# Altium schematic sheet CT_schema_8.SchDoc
size 391 x 238 mm
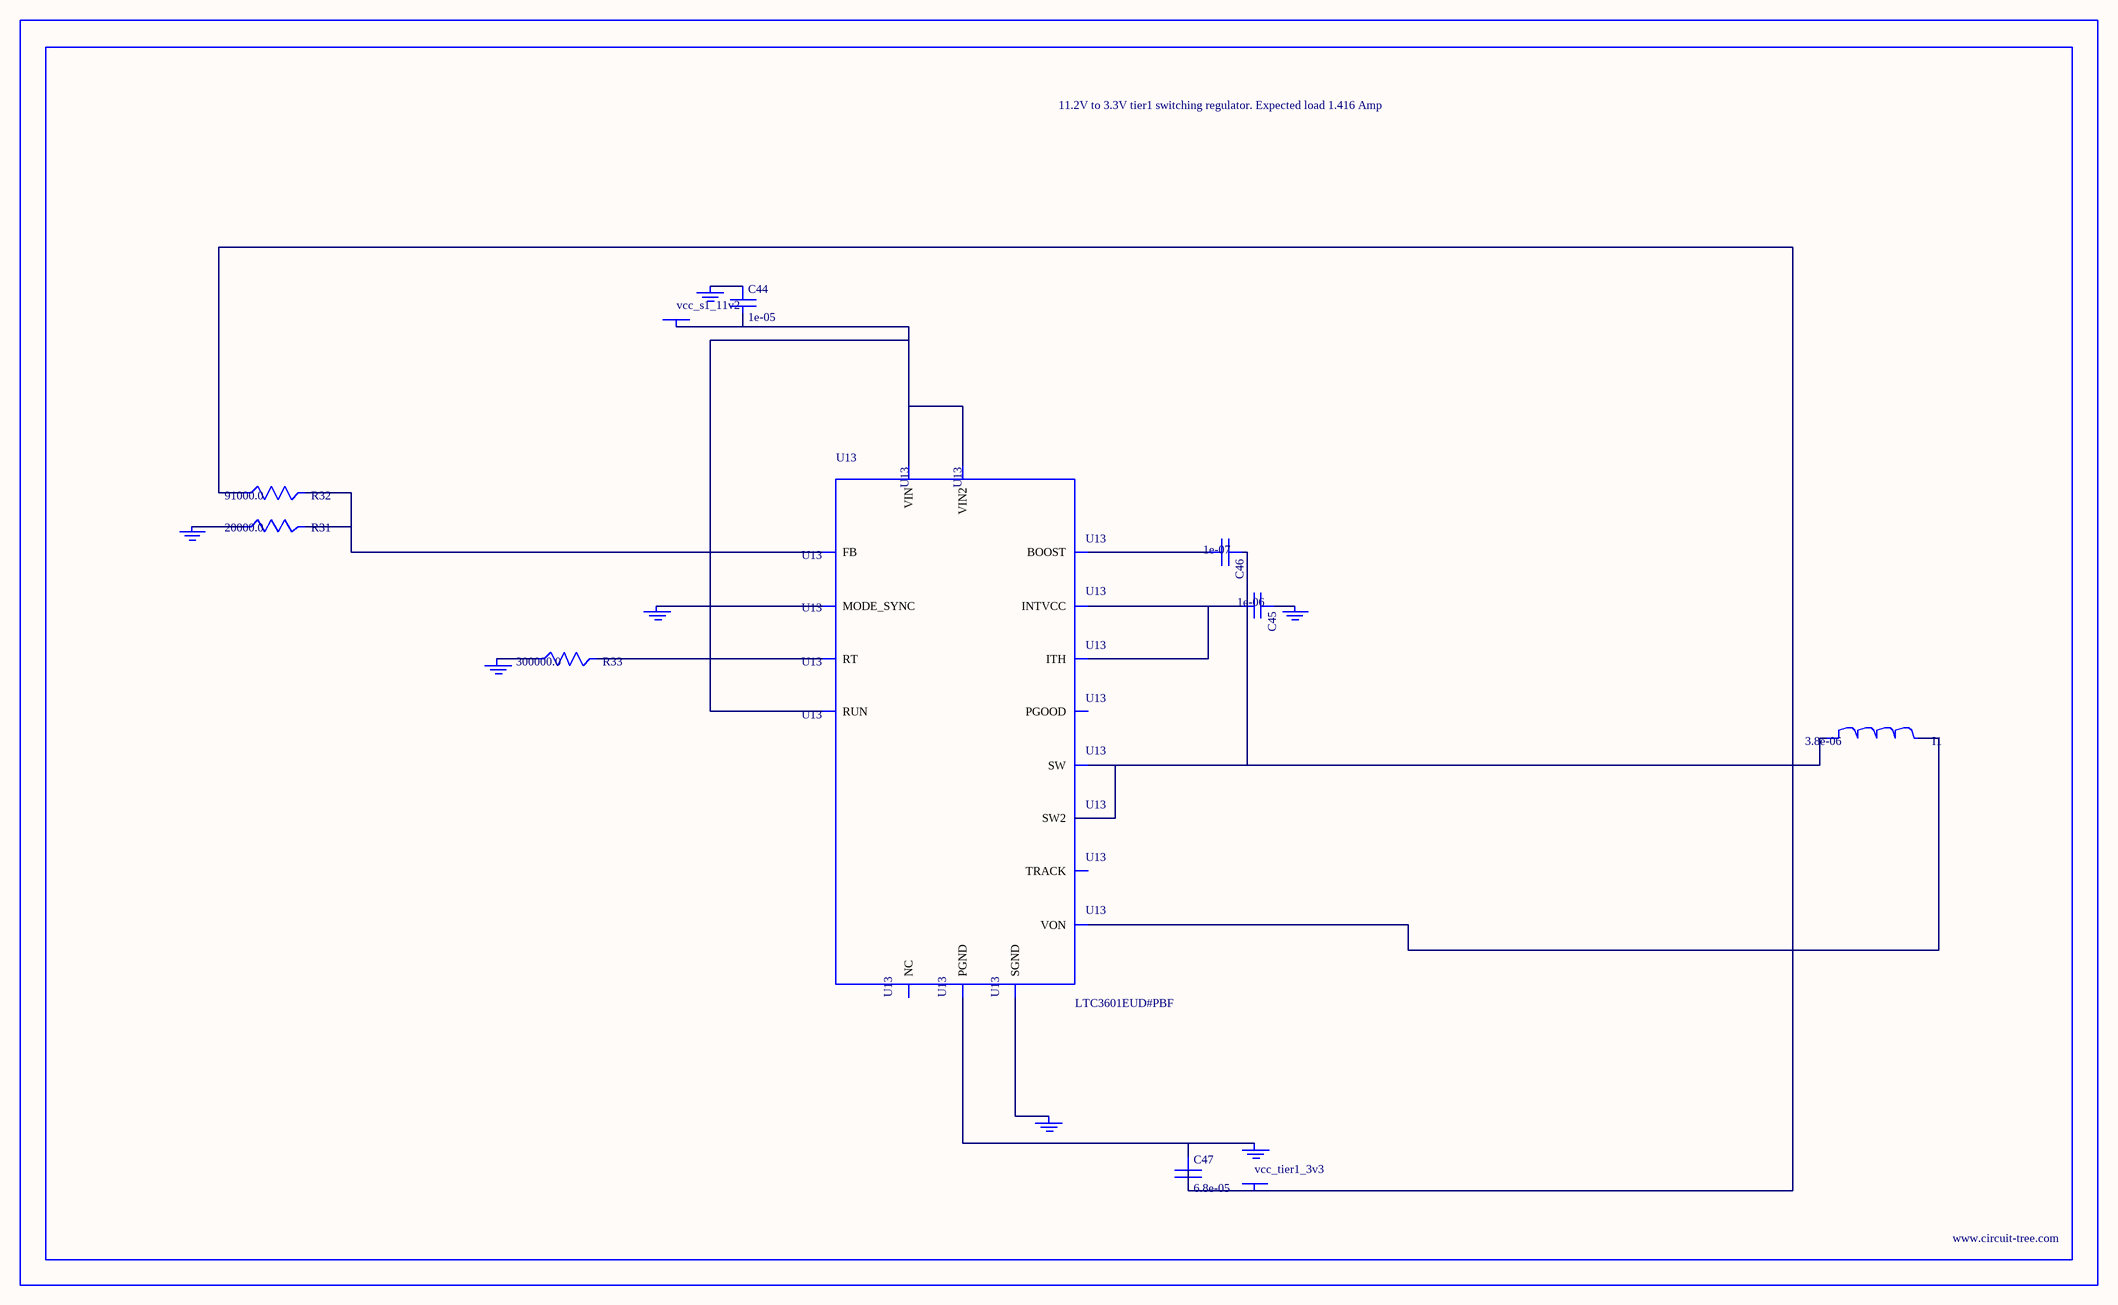
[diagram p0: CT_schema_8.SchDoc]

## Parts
BORDER7  (no value)
C44  1e-05  [C0805]
C45  1e-06  [C0603]
C46  1e-07  [C0402]
C47  6.8e-05  [2220]
GND_INSTANCE_7_0  (no value)
GND_INSTANCE_7_1  (no value)
GND_INSTANCE_7_2  (no value)
GND_INSTANCE_7_3  (no value)
GND_INSTANCE_7_4  (no value)
GND_INSTANCE_7_5  (no value)
GND_INSTANCE_7_6  (no value)
I1  3.8e-06  [DR1040]
POWER_INSTANCE_7_0  vcc_s1_11v2
POWER_INSTANCE_7_1  vcc_tier1_3v3
R31  20000.0  [R0603]
R32  91000.0  [R0603]
R33  300000.0  [R0603]
U13  LTC3601EUD#PBF  [QFN-16_EP]

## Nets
NetC44_1: C44.1 GND_INSTANCE_7_5.0(GND)
NetC44_2: C44.2 POWER_INSTANCE_7_0.0(PWR) U13.14(RUN) U13.15(VIN) U13.16(VIN2)
NetC45_1: C45.1 GND_INSTANCE_7_1.0(GND)
NetC45_2: C45.2 U13.7(INTVCC) U13.12(ITH)
NetC46_1: C46.1 I1.1 U13.3(SW) U13.4(SW2)
NetC46_2: C46.2 U13.6(BOOST)
NetC47_1: C47.1 GND_INSTANCE_7_6.0(GND) U13.17(PGND)
NetC47_2: C47.2 I1.2 POWER_INSTANCE_7_1.0(PWR) R32.1 U13.8(VON)
NetGND_INSTANCE_7_0_0: GND_INSTANCE_7_0.0(GND) U13.1(MODE_SYNC)
NetGND_INSTANCE_7_2_0: GND_INSTANCE_7_2.0(GND) U13.9(SGND)
NetGND_INSTANCE_7_3_0: GND_INSTANCE_7_3.0(GND) R33.1
NetGND_INSTANCE_7_4_0: GND_INSTANCE_7_4.0(GND) R31.1
NetR31_2: R31.2 R32.2 U13.11(FB)
NetR33_2: R33.2 U13.10(RT)

Not connected (* = marked no-connect by the designer): U13 2(PGOOD) 5(NC) 13(TRACK)

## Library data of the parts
BORDER7 = BORDER_PAGE7
C44 = C0805C106K8RACTU
C45 = C0603C105K3RACTU
C46 = C0402C104K3RACTU
C47 = C5750X5R1A686M
GND_INSTANCE_7_0-GND_INSTANCE_7_6 = GND
I1 = DR1040-3R8-R
POWER_INSTANCE_7_0 POWER_INSTANCE_7_1 = PWR
R31 = RC0603JR-0720KL
R32 = RC0603JR-0791KL
R33 = RC0603JR-07300KL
